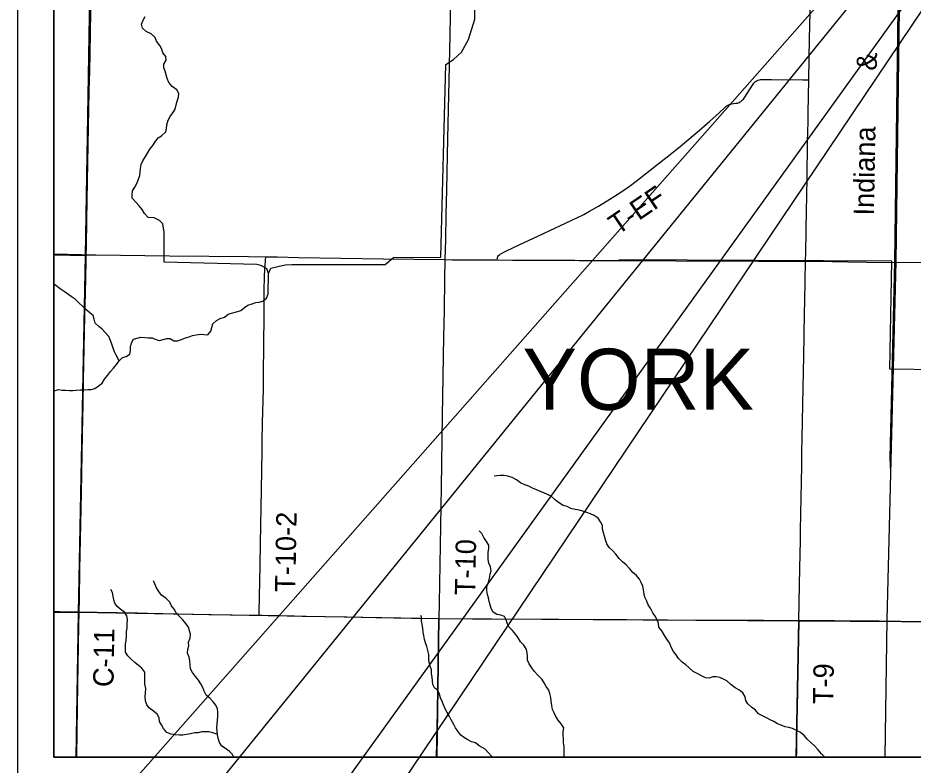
# Model space of a CAD drawing. Extents: x -21.7 to 34, y 0 to 22.
# Drawn here: x 23.417 to 25.914, y 14.078 to 16.163 of the extents above; entities that cross this region are included whole.
import ezdxf

# ---------------------------------------------------------------- set-up
doc = ezdxf.new("R2010")
doc.units = 0
for name, color, linetype in [('Default', 7, 'Continuous'), ('GM_X_County_Road', 7, 'Continuous'), ('GM_X_County_Road_Text', 7, 'Continuous'), ('GM_X_Interchange_Ramps', 7, 'Continuous'), ('GM_X_Minor_River', 7, 'Continuous'), ('GM_X_Rail_Line', 7, 'Continuous'), ('GM_X_Rail_Line_Text', 7, 'Continuous'), ('GM_X_Township_Road', 7, 'Continuous'), ('GM_X_Township_Road_Text', 7, 'Continuous'), ('GM_X_Township_Text', 7, 'Continuous'), ('SH_Data', 7, 'Continuous'), ('SH_Text', 7, 'Continuous')]:
    doc.layers.add(name, color=color, linetype=linetype)

msp = doc.modelspace()

# ---------------------------------------------------------------- linework, layer by layer
at = {"layer": 'Default'}
for points in [[(23.5167, 16.5057), (23.5167, 15.5023), (23.6052, 15.5005), (23.6222, 16.5033)], [(23.5167, 15.5023), (23.5167, 14.5047), (23.5861, 14.5034), (23.6052, 15.5005)], [(23.5167, 14.5047), (23.5167, 14.1), (23.5788, 14.1), (23.5861, 14.5034)], [(23.5788, 14.1), (24.5853, 14.1), (24.5915, 14.4863), (23.5861, 14.5034)], [(24.5853, 14.1), (25.588, 14.1), (25.5956, 14.4795), (24.5915, 14.4863)], [(25.588, 14.1), (26.5915, 14.1), (26.5986, 14.4731), (25.5956, 14.4795)]]:
    msp.add_lwpolyline(points, close=True, dxfattribs=at)
at = {"layer": 'GM_X_County_Road'}
for points in [[(23.6073, 15.5024), (23.6081, 15.5243), (23.6092, 15.5989), (23.6113, 15.7077), (23.6159, 15.9595), (23.617, 16.0154), (23.6181, 16.0651), (23.619, 16.1211), (23.6211, 16.2423), (23.6219, 16.2858), (23.6226, 16.3231), (23.6235, 16.3852), (23.6249, 16.4381), (23.6256, 16.4644)], [(23.5167, 15.5053), (23.5555, 15.5044), (23.5928, 15.503), (23.6073, 15.5024)], [(23.5878, 14.5055), (23.5883, 14.5423), (23.5896, 14.6231), (23.594, 14.8376), (23.5973, 15.0023), (23.5988, 15.0862), (23.5999, 15.1515), (23.6037, 15.3317), (23.6048, 15.3938), (23.6067, 15.484), (23.6073, 15.5024)], [(23.6073, 15.5024), (23.6341, 15.502), (23.8392, 15.4997), (24.0598, 15.4971), (24.1083, 15.4967)], [(24.1083, 15.4967), (24.1127, 15.4966), (24.1406, 15.4961), (24.1997, 15.4949), (24.4358, 15.4913), (24.6092, 15.4887)], [(24.6092, 15.4887), (24.6285, 15.4885), (24.7541, 15.4878)], [(24.7541, 15.4878), (24.7963, 15.4876), (24.9237, 15.4869), (24.9548, 15.4869), (24.9641, 15.4872), (24.9702, 15.4874), (24.9826, 15.4867), (25.0012, 15.4864), (25.0634, 15.4864), (25.1442, 15.486), (25.253, 15.4853), (25.4829, 15.4846), (25.5389, 15.4838), (25.6145, 15.484)], [(25.6145, 15.484), (25.6886, 15.4831), (25.7322, 15.4829), (25.785, 15.4821), (25.9404, 15.4804), (26.0088, 15.48), (26.0399, 15.4796), (26.3197, 15.4763), (26.4068, 15.4754), (26.4628, 15.4746), (26.5778, 15.4735), (26.6897, 15.4735), (26.7613, 15.474), (26.895, 15.4751), (27.1157, 15.4769), (27.1655, 15.4774), (27.2867, 15.4786), (27.3614, 15.4796), (27.3714, 15.4798)], [(23.5167, 14.5072), (23.5326, 14.5068), (23.5668, 14.5057), (23.5878, 14.5055)], [(23.5807, 14.1), (23.582, 14.1725), (23.5841, 14.303), (23.5869, 14.4678), (23.5878, 14.5055)], [(23.5878, 14.5055), (23.6165, 14.5051), (23.6382, 14.5046), (23.7501, 14.5026), (23.7781, 14.5018), (23.949, 14.4985), (24.0143, 14.4974), (24.064, 14.4966), (24.0901, 14.4961)], [(24.0901, 14.4961), (24.0982, 14.4959), (24.1448, 14.4952), (24.1882, 14.4943), (24.2099, 14.494), (24.3342, 14.4915), (24.4151, 14.4901), (24.5145, 14.4882), (24.5923, 14.4867)], [(24.5923, 14.4867), (24.6854, 14.4862), (24.7383, 14.4859), (24.9248, 14.485), (25.1144, 14.484), (25.1611, 14.4837), (25.2015, 14.4837), (25.2294, 14.4834), (25.4004, 14.4826), (25.4967, 14.4821), (25.5277, 14.4818), (25.5958, 14.4815)], [(25.5958, 14.4815), (25.6644, 14.4811), (25.6954, 14.4811), (25.7576, 14.4806), (25.8197, 14.4801), (25.8788, 14.4799), (25.9627, 14.4791), (26.0311, 14.479), (26.0995, 14.4784), (26.1679, 14.4781), (26.255, 14.4775), (26.4042, 14.4765), (26.513, 14.476), (26.6187, 14.4755), (26.6965, 14.4758), (26.8923, 14.4765), (27.0291, 14.4769), (27.0913, 14.4771), (27.2374, 14.477), (27.3431, 14.4775), (27.3462, 14.4775), (27.355, 14.4777)]]:
    msp.add_lwpolyline(points, dxfattribs=at)
at = {"layer": 'GM_X_Interchange_Ramps'}
msp.add_lwpolyline([(23.5167, 18.5138), (23.5167, 14.1), (27.5987, 14.1)], dxfattribs=at)
at = {"layer": 'GM_X_Minor_River'}
for points in [[(24.1157, 15.4505), (24.1225, 15.4647), (24.1423, 15.4696), (24.1622, 15.4741), (24.1812, 15.4756), (24.1982, 15.4752), (24.4418, 15.4747), (24.4643, 15.495), (24.5971, 15.4958), (24.6104, 16.0334), (24.6316, 16.047), (24.6541, 16.0677), (24.6743, 16.1033), (24.6915, 16.1595), (24.6914, 16.2191), (24.6895, 16.2518), (24.6818, 16.2815), (24.6888, 16.3019), (24.7005, 16.3195), (24.7498, 16.3958), (24.757, 16.4932), (24.7767, 16.4927)], [(23.8247, 15.5655), (23.8212, 15.5885), (23.8115, 15.5982), (23.7973, 15.605), (23.7798, 15.606), (23.7702, 15.6173), (23.7629, 15.6288), (23.7547, 15.6389), (23.7459, 15.6493), (23.7359, 15.6605), (23.7354, 15.67), (23.7364, 15.681), (23.7427, 15.6907), (23.7486, 15.7009), (23.7531, 15.7129), (23.7567, 15.7238), (23.7577, 15.7337), (23.7583, 15.7435), (23.7605, 15.7545), (23.7649, 15.7643), (23.7724, 15.7762), (23.7783, 15.786), (23.785, 15.7968), (23.7928, 15.8073), (23.7995, 15.8178), (23.8077, 15.8286), (23.8177, 15.8344), (23.829, 15.8452), (23.8315, 15.855), (23.8325, 15.8648), (23.8362, 15.878), (23.8418, 15.8885), (23.8492, 15.8982), (23.8552, 15.9091), (23.8581, 15.9204), (23.861, 15.9306), (23.8646, 15.9419), (23.8657, 15.9529), (23.8598, 15.9629), (23.8475, 15.9723), (23.8375, 15.9828), (23.8332, 15.9939), (23.8276, 16.0145), (23.8237, 16.0244), (23.8239, 16.0347), (23.8303, 16.0456), (23.8294, 16.0558), (23.8213, 16.0662), (23.8185, 16.0766), (23.8126, 16.0869), (23.8034, 16.0981), (23.7995, 16.1085), (23.7883, 16.1186), (23.7741, 16.1258), (23.7644, 16.1351), (23.7613, 16.1462), (23.7661, 16.1571), (23.7713, 16.1676)], [(24.1151, 15.3935), (24.1157, 15.4505), (24.1121, 15.4612), (24.1055, 15.467), (24.0946, 15.4722), (24.0836, 15.4747), (23.8243, 15.482), (23.8247, 15.5655)], [(26.1131, 15.0998), (26.1093, 15.1519), (26.107, 15.1577), (26.1027, 15.1604), (26.0955, 15.1601), (25.9855, 15.1618), (25.9844, 15.1808), (25.8494, 15.1827), (25.8553, 15.484), (25.0932, 15.4885)], [(23.6995, 15.2062), (23.6907, 15.222), (23.686, 15.2316), (23.6825, 15.2415), (23.6789, 15.253), (23.6754, 15.263), (23.67, 15.2745), (23.6611, 15.2845), (23.6518, 15.2942), (23.6421, 15.3017), (23.6321, 15.3114), (23.6297, 15.3228), (23.6269, 15.3324), (23.6169, 15.3402), (23.6065, 15.3495), (23.5972, 15.3592), (23.5868, 15.3682), (23.576, 15.3783), (23.5656, 15.3861), (23.5454, 15.3995), (23.5342, 15.4073), (23.5223, 15.4163), (23.5167, 15.4203)], [(23.5167, 15.1223), (23.5177, 15.1226), (23.5295, 15.1262), (23.5405, 15.1244), (23.5503, 15.1242), (23.5602, 15.1236), (23.5701, 15.1237), (23.5795, 15.1243), (23.5902, 15.1252), (23.602, 15.1257), (23.6115, 15.1259), (23.621, 15.1264), (23.6309, 15.1288), (23.6409, 15.1351), (23.6517, 15.1443), (23.658, 15.1548), (23.6666, 15.1652), (23.6749, 15.1761), (23.6834, 15.1861), (23.6916, 15.1962), (23.6995, 15.2062), (23.7084, 15.2159), (23.7191, 15.2187), (23.7291, 15.2246), (23.7312, 15.2348), (23.7307, 15.2446), (23.7333, 15.2564), (23.7396, 15.2665), (23.7495, 15.27), (23.7594, 15.2725), (23.7704, 15.2711), (23.7803, 15.2705), (23.7913, 15.2706), (23.8018, 15.2658), (23.8116, 15.2626), (23.8223, 15.2654), (23.8318, 15.2686), (23.8417, 15.2683), (23.8521, 15.262), (23.8624, 15.2618), (23.8731, 15.2657), (23.8842, 15.2704), (23.8941, 15.2729), (23.9041, 15.2772), (23.9144, 15.2789), (23.927, 15.2809), (23.9368, 15.2795), (23.9463, 15.2793), (23.9552, 15.2889), (23.9581, 15.2991), (23.9602, 15.3093), (23.9703, 15.3186), (23.9807, 15.3241), (23.9929, 15.3283), (24.003, 15.3368), (24.0129, 15.3397), (24.0267, 15.3431), (24.0385, 15.3471), (24.0486, 15.3552), (24.0582, 15.3618), (24.0701, 15.3657), (24.0804, 15.3689), (24.0899, 15.3698), (24.1002, 15.373), (24.1103, 15.3811), (24.1151, 15.3935)], [(25.6102, 14.1609), (25.6002, 14.1687), (25.5904, 14.1731), (25.5781, 14.1798), (25.5679, 14.1831), (25.5573, 14.1844), (25.546, 14.1889), (25.5363, 14.1933), (25.5258, 14.1992), (25.5153, 14.2044), (25.5055, 14.2099), (25.4939, 14.2151), (25.4831, 14.2214), (25.4742, 14.2311), (25.463, 14.2397), (25.4533, 14.2486), (25.4475, 14.2583), (25.4458, 14.2682), (25.4393, 14.2793), (25.4277, 14.2876), (25.4176, 14.2935), (25.406, 14.3028), (25.3949, 14.313), (25.3852, 14.3177), (25.3754, 14.3221), (25.3648, 14.3243), (25.3553, 14.3241), (25.345, 14.3205), (25.3352, 14.3211), (25.3243, 14.3271), (25.3123, 14.3338), (25.3011, 14.3394), (25.2899, 14.3495), (25.2802, 14.358), (25.2698, 14.3651), (25.2602, 14.3756), (25.2528, 14.3856), (25.2462, 14.3953), (25.24, 14.4053), (25.2343, 14.4194), (25.2269, 14.4291), (25.22, 14.4414), (25.2134, 14.4522), (25.2049, 14.4626), (25.2037, 14.4733), (25.2005, 14.4832), (25.195, 14.4932), (25.1884, 14.5028), (25.1822, 14.5136), (25.1753, 14.5255), (25.1717, 14.5355), (25.1659, 14.5466), (25.1639, 14.5562), (25.1618, 14.5668), (25.1598, 14.5771), (25.1559, 14.5875), (25.1508, 14.5971), (25.1423, 14.6067), (25.1326, 14.6153), (25.1226, 14.6262), (25.1134, 14.6366), (25.1034, 14.6452), (25.0941, 14.6549), (25.0849, 14.6665), (25.0756, 14.6766), (25.066, 14.6855), (25.0598, 14.6959), (25.0559, 14.7062), (25.0534, 14.7165), (25.0502, 14.7261), (25.0478, 14.736), (25.0481, 14.7467), (25.0422, 14.757), (25.0353, 14.7667), (25.0241, 14.7749), (25.0139, 14.7789), (25.0038, 14.7826), (24.9929, 14.787), (24.9823, 14.7899), (24.9717, 14.7916), (24.9596, 14.7938), (24.9492, 14.8001), (24.9382, 14.8023), (24.9251, 14.8109), (24.9155, 14.8187), (24.9047, 14.8281), (24.8946, 14.8336), (24.8837, 14.8376), (24.8724, 14.8428), (24.8619, 14.8473), (24.8521, 14.8513), (24.842, 14.856), (24.8307, 14.8597), (24.8187, 14.8653), (24.8075, 14.8739), (24.7959, 14.8802), (24.7835, 14.8847), (24.7725, 14.8865), (24.763, 14.8859), (24.7527, 14.885), (24.7459, 14.8848)], [(24.9403, 14.1), (24.9404, 14.1053), (24.9403, 14.1166), (24.9406, 14.1284), (24.9393, 14.1402), (24.9385, 14.152), (24.938, 14.1615), (24.9378, 14.1717), (24.94, 14.1823), (24.9326, 14.1927), (24.9238, 14.2032), (24.9175, 14.2136), (24.9125, 14.2239), (24.9085, 14.2335), (24.9061, 14.2442), (24.9049, 14.256), (24.9032, 14.2663), (24.9005, 14.2774), (24.8976, 14.2869), (24.8903, 14.2969), (24.8852, 14.3077), (24.8783, 14.3181), (24.8675, 14.329), (24.8572, 14.3398), (24.8509, 14.3498), (24.8432, 14.3606), (24.8382, 14.3706), (24.838, 14.3812), (24.8371, 14.3911), (24.8354, 14.4007), (24.8281, 14.4122), (24.8193, 14.4223), (24.8123, 14.4327), (24.8061, 14.4423), (24.7968, 14.4532), (24.7868, 14.4636), (24.7821, 14.4736), (24.7786, 14.4832), (24.7742, 14.4928), (24.7637, 14.4968), (24.7527, 14.4982), (24.743, 14.5045), (24.7368, 14.5149), (24.734, 14.5248), (24.7316, 14.5343), (24.7299, 14.5443), (24.7271, 14.5538), (24.7251, 14.5656), (24.7246, 14.5763), (24.7294, 14.5883), (24.732, 14.5996), (24.7345, 14.6106), (24.737, 14.6204), (24.7354, 14.6311), (24.7307, 14.6418), (24.7287, 14.6521), (24.7285, 14.662), (24.7291, 14.6726), (24.7309, 14.6824), (24.7307, 14.6919), (24.7245, 14.7023), (24.7168, 14.7135), (24.7106, 14.7239), (24.704, 14.7316)], [(24.0194, 14.1), (24.0151, 14.1075), (24.0062, 14.1171), (23.9958, 14.1238), (23.9857, 14.1309), (23.9791, 14.1409), (23.9756, 14.1531), (23.9735, 14.1627), (23.9722, 14.1726), (23.9721, 14.1832), (23.9724, 14.1935), (23.9737, 14.2037), (23.9747, 14.2139), (23.9742, 14.2253), (23.9733, 14.2352), (23.9686, 14.2448), (23.9617, 14.2544), (23.9528, 14.2641), (23.942, 14.2735), (23.9362, 14.2838), (23.9322, 14.2942), (23.9272, 14.3045), (23.9202, 14.3146), (23.9121, 14.325), (23.9036, 14.3362), (23.8982, 14.347), (23.8973, 14.3576), (23.8964, 14.369), (23.8944, 14.3789), (23.8901, 14.39), (23.8904, 14.401), (23.8933, 14.4112), (23.8923, 14.4207), (23.8972, 14.432), (23.8978, 14.443), (23.8958, 14.4529), (23.8926, 14.4629), (23.8848, 14.4729), (23.8771, 14.4837), (23.8675, 14.4923), (23.8582, 14.5031), (23.8531, 14.5127), (23.8454, 14.5224), (23.8403, 14.5324), (23.8299, 14.5425), (23.8173, 14.5522), (23.8096, 14.5627), (23.8026, 14.5746), (23.7965, 14.5888), (23.7947, 14.5922)], [(23.9705, 14.1646), (23.9604, 14.1675), (23.9498, 14.1708), (23.9396, 14.1707), (23.9293, 14.1709), (23.9194, 14.1681), (23.9099, 14.1683), (23.8981, 14.1651), (23.8874, 14.1635), (23.8771, 14.1614), (23.8673, 14.1613), (23.8555, 14.1623), (23.8442, 14.1641), (23.8322, 14.1693), (23.8233, 14.1797), (23.8171, 14.1901), (23.8116, 14.1997), (23.8107, 14.21), (23.8053, 14.2204), (23.7949, 14.2282), (23.7837, 14.2368), (23.7763, 14.2464), (23.7724, 14.2572), (23.7715, 14.2689), (23.7725, 14.2792), (23.7736, 14.2917), (23.7712, 14.3035), (23.7708, 14.3179), (23.771, 14.3278), (23.7709, 14.3377), (23.7628, 14.3485), (23.7527, 14.3563), (23.7431, 14.3645), (23.733, 14.3738), (23.7234, 14.3824), (23.7164, 14.3932), (23.717, 14.4034), (23.7173, 14.4148), (23.7183, 14.4262), (23.7198, 14.4386), (23.72, 14.45), (23.7211, 14.4622), (23.7213, 14.472), (23.722, 14.4845), (23.7207, 14.4944), (23.7145, 14.5044), (23.7044, 14.5111), (23.694, 14.5205), (23.6874, 14.5301), (23.6846, 14.5396), (23.6829, 14.5496), (23.6805, 14.5595), (23.6761, 14.5676)], [(24.7403, 14.1), (24.7381, 14.1026), (24.73, 14.1123), (24.7208, 14.122), (24.7035, 14.1314), (24.6931, 14.1397), (24.6822, 14.1426), (24.6724, 14.1481), (24.6627, 14.1544), (24.6523, 14.1618), (24.6445, 14.1723), (24.6372, 14.1819), (24.6329, 14.1915), (24.6252, 14.2038), (24.6209, 14.2138), (24.6147, 14.2249), (24.6092, 14.2353), (24.6045, 14.2457), (24.6002, 14.2552), (24.5959, 14.266), (24.5931, 14.2755), (24.5884, 14.2859), (24.5787, 14.2933), (24.5744, 14.3033), (24.5735, 14.3128), (24.5722, 14.3234), (24.5702, 14.3337), (24.5704, 14.3436), (24.5665, 14.3539), (24.5641, 14.3646), (24.5632, 14.3745), (24.5631, 14.3863), (24.5603, 14.3977), (24.5579, 14.4088), (24.5536, 14.4188), (24.5515, 14.4283), (24.5495, 14.4394), (24.5471, 14.4489), (24.5462, 14.4603), (24.5446, 14.4706), (24.5429, 14.4805), (24.5424, 14.4904), (24.541, 14.4954)], [(25.6679, 14.1), (25.6587, 14.1093), (25.6491, 14.1205), (25.6392, 14.1317), (25.6287, 14.1407), (25.6191, 14.15), (25.6102, 14.1609)]]:
    msp.add_lwpolyline(points, dxfattribs=at)
at = {"layer": 'GM_X_Rail_Line'}
for points in [[(25.8368, 14.1), (25.8424, 14.4841), (25.8672, 15.4825), (25.8776, 16.2603), (25.8795, 16.4862), (25.8906, 16.927), (25.8907, 16.9438), (25.8961, 17.4845), (25.9239, 18.7551), (25.935, 19.5978), (25.9554, 20.5461), (25.9616, 20.9)], [(25.8526, 14.8964), (25.8499, 14.9355), (25.8634, 15.4826), (25.8739, 16.2603), (25.8757, 16.4863), (25.8868, 16.9271), (25.887, 16.9438), (25.8904, 17.1251), (25.8905, 17.1392), (25.893, 17.1728)]]:
    msp.add_lwpolyline(points, dxfattribs=at)
at = {"layer": 'GM_X_Township_Road'}
for points in [[(24.6092, 15.4887), (24.6104, 15.5436), (24.612, 15.615), (24.6132, 15.6834), (24.6165, 15.8264), (24.6191, 15.9476), (24.6196, 15.9881), (24.6206, 16.0316), (24.6224, 16.1155), (24.6247, 16.2274), (24.6255, 16.2647), (24.6276, 16.3672), (24.6298, 16.4729), (24.6301, 16.4891)], [(25.6234, 15.9906), (25.6244, 16.0508), (25.6255, 16.1037), (25.6295, 16.2964), (25.632, 16.4331), (25.6331, 16.4875)], [(25.3003, 15.835), (25.3118, 15.8446), (25.3471, 15.875), (25.3633, 15.8896), (25.3859, 15.9109), (25.3907, 15.9149), (25.3932, 15.9167), (25.3985, 15.9199), (25.4013, 15.9213), (25.4043, 15.9225), (25.4062, 15.9231), (25.4084, 15.9237), (25.4136, 15.9245), (25.4198, 15.9252), (25.4226, 15.9256), (25.4243, 15.9259), (25.426, 15.9264), (25.4291, 15.9275), (25.432, 15.9289), (25.4347, 15.9308), (25.4366, 15.9325), (25.4386, 15.9347), (25.4407, 15.937), (25.4445, 15.9419), (25.4514, 15.9523), (25.4665, 15.9759), (25.4701, 15.981), (25.4721, 15.9833), (25.4743, 15.9855), (25.4768, 15.9873), (25.4795, 15.9888), (25.4823, 15.9899), (25.4853, 15.9906), (25.4884, 15.9911), (25.4946, 15.9913), (25.5195, 15.9911), (25.6065, 15.9906), (25.6159, 15.9906), (25.6234, 15.9906)], [(25.6145, 15.484), (25.615, 15.5099), (25.6154, 15.5285), (25.6156, 15.5471), (25.6159, 15.5751), (25.6165, 15.6218), (25.6176, 15.6684), (25.6184, 15.715), (25.6201, 15.8176), (25.6212, 15.8736), (25.6218, 15.8984), (25.6234, 15.9906)], [(24.7541, 15.4878), (24.7547, 15.4917), (24.7551, 15.4948), (24.756, 15.4978), (24.7577, 15.5003), (24.76, 15.5022), (24.7626, 15.5039), (24.7763, 15.5114), (24.8015, 15.5237), (24.8693, 15.5548), (24.976, 15.6054), (24.9955, 15.6151), (25.0119, 15.624), (25.0361, 15.6379), (25.0681, 15.6572), (25.089, 15.6705), (25.1096, 15.6844), (25.1299, 15.6989), (25.1497, 15.714), (25.1985, 15.7524), (25.2279, 15.7754), (25.2641, 15.8047), (25.3003, 15.835)], [(23.5167, 15.5053), (23.5555, 15.5044), (23.5928, 15.503), (23.6073, 15.5024)], [(23.6073, 15.5024), (23.6341, 15.502), (23.8392, 15.4997), (24.0598, 15.4971), (24.1083, 15.4967)], [(24.1006, 15.0886), (24.1015, 15.1328), (24.1018, 15.1639), (24.1028, 15.2572), (24.1036, 15.3256), (24.1037, 15.3691), (24.1036, 15.4034), (24.1044, 15.4407), (24.1054, 15.4625), (24.1071, 15.4842), (24.1074, 15.4873), (24.1083, 15.4967)], [(24.1083, 15.4967), (24.1127, 15.4966), (24.1406, 15.4961), (24.1997, 15.4949), (24.4358, 15.4913), (24.6092, 15.4887)], [(24.5923, 14.4867), (24.593, 14.5302), (24.5984, 14.8535), (24.6015, 15.0524), (24.6054, 15.2732), (24.6067, 15.3477), (24.6079, 15.4348), (24.6092, 15.4887)], [(24.6092, 15.4887), (24.6285, 15.4885), (24.7541, 15.4878)], [(24.7541, 15.4878), (24.7963, 15.4876), (24.9237, 15.4869), (24.9548, 15.4869), (24.9641, 15.4872), (24.9702, 15.4874), (24.9826, 15.4867), (25.0012, 15.4864), (25.0634, 15.4864), (25.1442, 15.486), (25.253, 15.4853), (25.4829, 15.4846), (25.5389, 15.4838), (25.6145, 15.484)], [(25.5958, 14.4815), (25.5975, 14.5804), (25.5985, 14.6271), (25.5998, 14.7048), (25.6003, 14.7328), (25.6011, 14.7794), (25.6037, 14.9131), (25.6043, 14.9535), (25.6052, 14.9908), (25.6057, 15.0374), (25.6085, 15.1773), (25.6091, 15.2178), (25.6116, 15.339), (25.6122, 15.3732), (25.6145, 15.484)], [(25.6145, 15.484), (25.6886, 15.4831), (25.7322, 15.4829), (25.785, 15.4821), (25.9404, 15.4804), (26.0088, 15.48), (26.0399, 15.4796), (26.3197, 15.4763), (26.4068, 15.4754), (26.4628, 15.4746), (26.5778, 15.4735), (26.6897, 15.4735), (26.7613, 15.474), (26.895, 15.4751), (27.1157, 15.4769), (27.1655, 15.4774), (27.2867, 15.4786), (27.3614, 15.4796), (27.3714, 15.4798)], [(24.0901, 14.4961), (24.0902, 14.5045), (24.0923, 14.6351), (24.0933, 14.6973), (24.096, 14.8466), (24.0979, 14.9555), (24.0983, 14.9897), (24.0993, 15.027), (24.1002, 15.0706), (24.1006, 15.0886)], [(24.5849, 14.1), (24.5874, 14.2287), (24.59, 14.3686), (24.5915, 14.4338), (24.5923, 14.4867)], [(25.5893, 14.1), (25.5895, 14.114), (25.5902, 14.1514), (25.5912, 14.1918), (25.5921, 14.2478), (25.5925, 14.2757), (25.593, 14.313), (25.5939, 14.3752), (25.595, 14.4343), (25.5958, 14.4815)]]:
    msp.add_lwpolyline(points, dxfattribs=at)
at = {"layer": 'SH_Data'}
for p, q in [((23.5167, 20.9), (23.5167, 14.1)), ((23.5167, 14.1), (30.3167, 14.1)), ((23.5167, 14.1), (23.5167, 14.1))]:
    msp.add_line(p, q, dxfattribs=at)
for points in [[(23.4167, 21), (30.4167, 21), (30.4167, 14), (23.4167, 14)], [(23.5167, 20.9), (30.3167, 20.9), (30.3167, 14.1), (23.5167, 14.1)]]:
    msp.add_lwpolyline(points, close=True, dxfattribs=at)
at = {"layer": 'SH_Text'}
for points in [[(23.5845, 13.5445), (26.7756, 17.4787), (23.5845, 13.8593)], [(23.5845, 12.6836), (26.8092, 17.4787), (23.5845, 12.9954)]]:
    msp.add_lwpolyline(points, close=True, dxfattribs=at)

# ---------------------------------------------------------------- texts
at = {"layer": 'GM_X_County_Road_Text'}
msp.add_text('C-11', height=0.05682, rotation=88.9714, dxfattribs=at).set_placement((23.6832, 14.2953))
at = {"layer": 'GM_X_Rail_Line_Text'}
for s, height, rotation, p in [('&', 0.0566, 88.666, (25.8127, 16.0159)), ('Indiana', 0.05663, 88.9677, (25.8049, 15.6115))]:
    msp.add_text(s, height=height, rotation=rotation, dxfattribs=at).set_placement(p)
at = {"layer": 'GM_X_Township_Road_Text'}
for s, rotation, p in [('T-EF', 34.2483, (25.0897, 15.5562)), ('T-10-2', 89.0099, (24.1906, 14.5607)), ('T-10', 88.9383, (24.6923, 14.5519)), ('T-9', 89.04, (25.6915, 14.2476))]:
    msp.add_text(s, height=0.05682, rotation=rotation, dxfattribs=at).set_placement(p)
at = {"layer": 'GM_X_Township_Text'}
msp.add_text('YORK', height=0.17045, rotation=0, dxfattribs=at).set_placement((24.8244, 15.0696))

doc.saveas('drawing.dxf')
